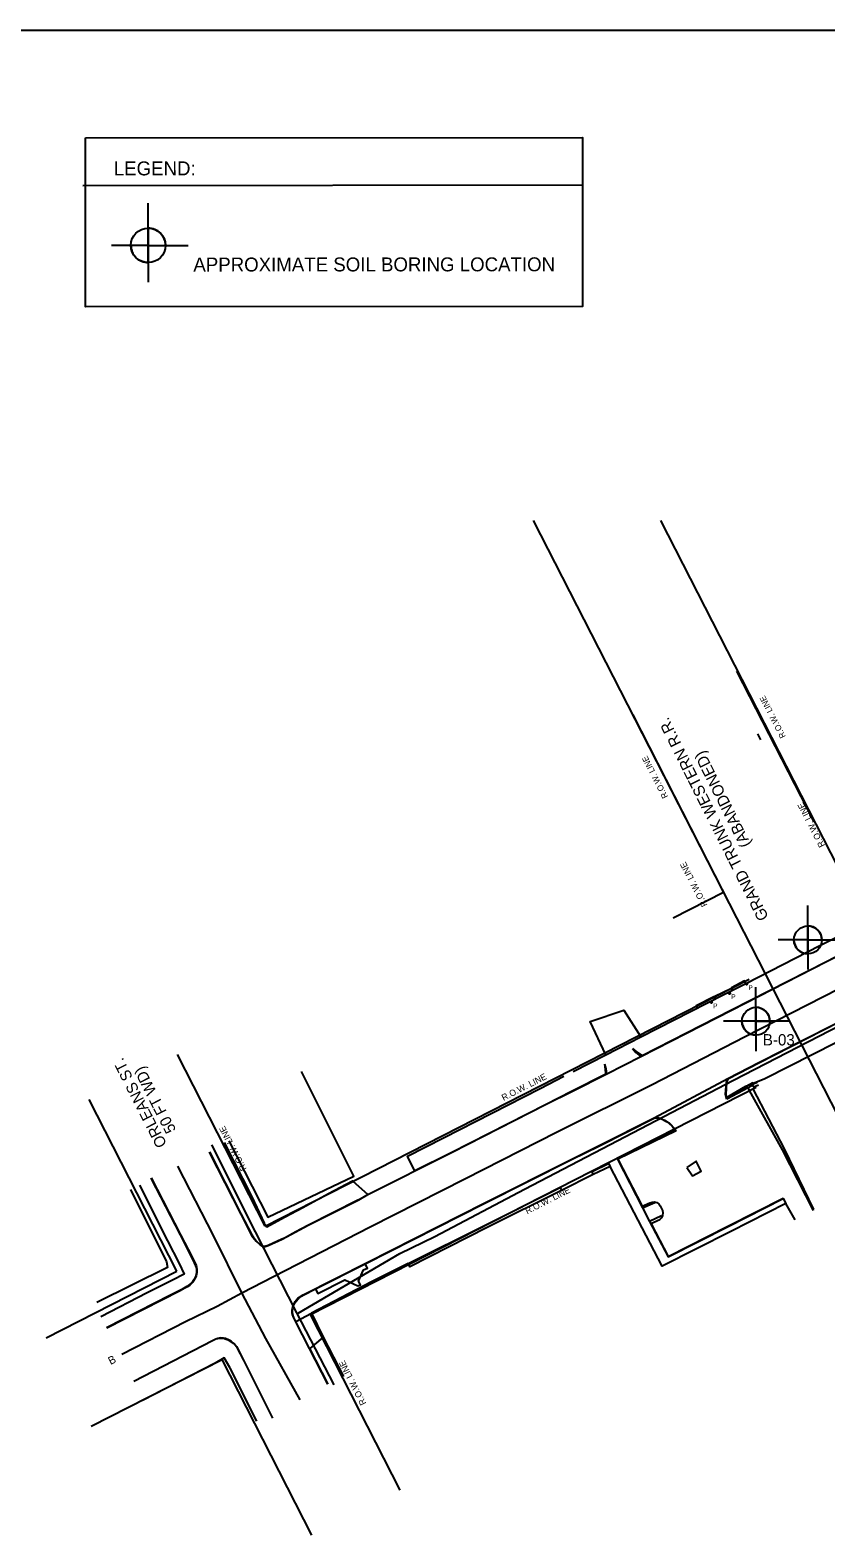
# Model space of a CAD drawing. Extents: x 19007.2 to 19038.3, y 21497.7 to 21516.9.
# Drawn here: x 19024.12 to 19030.11, y 21505.5 to 21516.85 of the extents above; entities that cross this region are included whole.
import ezdxf

# ---------------------------------------------------------------- set-up
doc = ezdxf.new("R2010")
doc.units = 0
for name, color, linetype in [('BORDER', 7, 'Continuous'), ('DETAIL_TEXT_DIMEN_PR', 7, 'Continuous'), ('G-ANNO-TTLB', 7, 'Continuous'), ('TYPICAL_TEXT_DIMEN_PR', 7, 'Continuous'), ('V-ANNO-TEXT', 7, 'Continuous'), ('V-BLDG-OTLN', 7, 'Continuous'), ('V-DEMO-PVMT', 7, 'Continuous'), ('V-PROP-RWAY', 7, 'Continuous'), ('V-PROP-RWAY-IDEN', 7, 'Continuous'), ('V-PVMT-CNTR', 7, 'Continuous'), ('V-PVMT-ROAD', 7, 'Continuous'), ('V-SITE-FEAT-DEMO', 7, 'Continuous'), ('V-SITE-FENC', 7, 'Continuous'), ('V-SITE-STRS', 7, 'Continuous'), ('V-SITE-WALK', 7, 'Continuous'), ('V-UTIL-OVHD', 7, 'Continuous')]:
    doc.layers.add(name, color=color, linetype=linetype)

msp = doc.modelspace()

# ---------------------------------------------------------------- linework, layer by layer
at = {"layer": 'G-ANNO-TTLB'}
msp.add_lwpolyline([(19036.518, 21497.739), (19007.175, 21497.739), (19007.175, 21516.854), (19036.518, 21516.854)], close=True, dxfattribs=at)
at = {"layer": 'TYPICAL_TEXT_DIMEN_PR'}
for p, q in [((19024.513, 21515.685), (19028.274, 21515.688)), ((19025.005, 21515.233), (19025.005, 21515.552)), ((19025.005, 21515.233), (19024.73, 21515.233)), ((19025.005, 21515.233), (19025.006, 21514.957)), ((19025.005, 21515.233), (19025.307, 21515.233)), ((19029.97, 21510.003), (19029.969, 21510.261)), ((19029.97, 21510.003), (19029.746, 21510.003)), ((19029.97, 21510.003), (19030.214, 21510.004)), ((19029.97, 21510.003), (19029.97, 21509.78)), ((19029.579, 21509.39), (19029.578, 21509.648)), ((19029.579, 21509.39), (19029.336, 21509.39)), ((19029.579, 21509.39), (19029.579, 21509.166)), ((19029.823, 21509.39), (19029.579, 21509.39))]:
    msp.add_line(p, q, dxfattribs=at)
msp.add_lwpolyline([(19024.532, 21516.044), (19028.273, 21516.046), (19028.274, 21514.773), (19024.533, 21514.77)], close=True, dxfattribs=at)
for points in [[(19025.005, 21515.363), (19025.005, 21515.233), (19025.135, 21515.233)], [(19025.006, 21515.103), (19025.005, 21515.233), (19024.875, 21515.233)], [(19029.97, 21510.109), (19029.97, 21510.003), (19030.075, 21510.003)], [(19029.97, 21509.898), (19029.97, 21510.003), (19029.864, 21510.003)], [(19029.579, 21509.495), (19029.579, 21509.39), (19029.684, 21509.39)], [(19029.579, 21509.284), (19029.579, 21509.39), (19029.473, 21509.39)]]:
    msp.add_lwpolyline(points, dxfattribs=at)
for centre, radius in [((19025.005, 21515.233), 0.13), ((19029.97, 21510.003), 0.105), ((19029.579, 21509.39), 0.105)]:
    msp.add_circle(centre, radius, dxfattribs=at)
for centre, radius, start, end in [((19025.005, 21515.233), 0.13, 0.0399, 90.0399), ((19025.005, 21515.233), 0.13, 180.0399, 270.0399), ((19029.97, 21510.003), 0.105, 0.0399, 90.0399), ((19029.97, 21510.003), 0.105, 180.0399, 270.0399), ((19029.579, 21509.39), 0.105, 0.0399, 90.0399), ((19029.579, 21509.39), 0.105, 180.0399, 270.0399)]:
    msp.add_arc(centre, radius, start, end, dxfattribs=at)
at = {"layer": 'V-BLDG-OTLN'}
for points in [[(19029.504, 21509.674), (19029.494, 21509.694), (19029.396, 21509.643), (19029.404, 21509.627)], [(19029.268, 21509.559), (19029.261, 21509.574), (19029.13, 21509.507), (19029.137, 21509.492)], [(19029.4, 21509.627), (19029.395, 21509.638), (19029.264, 21509.574), (19029.271, 21509.561)], [(19029.589, 21508.929), (19029.561, 21508.916), (19029.555, 21508.926), (19029.505, 21508.899), (19029.51, 21508.887), (19029.554, 21508.91), (19029.563, 21508.896), (19029.598, 21508.912)], [(19029.875, 21507.894), (19029.805, 21508.018), (19029.389, 21507.808), (19028.873, 21507.546), (19028.481, 21508.297), (19028.355, 21508.236), (19028.115, 21508.115), (19027.557, 21507.836), (19026.975, 21507.542), (19026.962, 21507.566), (19026.685, 21507.428), (19026.233, 21507.192), (19026.323, 21507.01), (19026.474, 21506.714)], [(19028.355, 21508.236), (19028.346, 21508.258), (19028.47, 21508.319), (19028.481, 21508.297)], [(19026.962, 21507.566), (19027.545, 21507.856), (19028.106, 21508.138), (19028.115, 21508.115)], [(19025.823, 21506.378), (19025.619, 21506.783), (19025.578, 21506.856), (19025.509, 21506.815), (19024.963, 21506.535)]]:
    msp.add_lwpolyline(points, dxfattribs=at)
at = {"layer": 'V-DEMO-PVMT'}
for points in [[(19028.193, 21508.862), (19028.458, 21508.995), (19028.585, 21509.06), (19028.712, 21509.125), (19029.395, 21509.474), (19030.111, 21509.839), (19030.748, 21510.163), (19030.799, 21510.192), (19031.091, 21510.345)], [(19028.204, 21509.012), (19028.449, 21509.137), (19028.713, 21509.274), (19029.337, 21509.592), (19029.504, 21509.674), (19030.06, 21509.961), (19030.619, 21510.24), (19030.563, 21510.344)], [(19028.651, 21509.186), (19028.68, 21509.16), (19028.723, 21509.133), (19029.394, 21509.477), (19030.11, 21509.841), (19030.685, 21510.139), (19030.722, 21510.155)], [(19028.4, 21508.455), (19028.813, 21508.662), (19029.367, 21508.959), (19029.601, 21509.079), (19030.324, 21509.447), (19030.834, 21509.706), (19030.982, 21509.779), (19031.298, 21509.941)], [(19029.358, 21508.819), (19029.354, 21508.84), (19029.36, 21508.93), (19029.373, 21508.96), (19029.602, 21509.076), (19030.323, 21509.445), (19030.835, 21509.705), (19030.983, 21509.777)], [(19028.649, 21509.185), (19028.674, 21509.155), (19028.712, 21509.125)], [(19028.192, 21508.863), (19028.449, 21508.993), (19028.446, 21509.03), (19028.442, 21509.066)], [(19028.458, 21508.995), (19028.453, 21509.031), (19028.442, 21509.066)], [(19029.361, 21508.803), (19029.351, 21508.841), (19029.358, 21508.93), (19029.367, 21508.959)], [(19028.401, 21508.453), (19028.813, 21508.66), (19028.82, 21508.662), (19028.833, 21508.664), (19028.847, 21508.662), (19028.873, 21508.652), (19028.908, 21508.633), (19028.924, 21508.622), (19028.948, 21508.6), (19028.958, 21508.588), (19028.964, 21508.58)], [(19028.813, 21508.662), (19028.841, 21508.661), (19028.854, 21508.659), (19028.874, 21508.654), (19028.892, 21508.646), (19028.903, 21508.639), (19028.925, 21508.624), (19028.938, 21508.613), (19028.961, 21508.588), (19028.978, 21508.566)], [(19028.964, 21508.58), (19028.974, 21508.567)]]:
    msp.add_lwpolyline(points, dxfattribs=at)
at = {"layer": 'V-PROP-RWAY'}
for p, q in [((19031.565, 21506), (19027.906, 21513.161)), ((19028.86, 21513.161), (19032.52, 21506.001)), ((19029.433, 21512.026), (19030.015, 21510.891)), ((19028.652, 21511.697), (19029.335, 21510.36)), ((19029.591, 21511.554), (19029.614, 21511.51)), ((19029.335, 21510.36), (19028.957, 21510.167)), ((19025.886, 21507.848), (19029.528, 21509.706)), ((19025.886, 21507.848), (19025.226, 21509.141)), ((19028.966, 21508.581), (19029.581, 21508.895)), ((19025.221, 21507.509), (19024.561, 21508.802)), ((19026.226, 21507.183), (19028.966, 21508.581)), ((19024.236, 21507.006), (19025.221, 21507.509)), ((19026.901, 21505.859), (19026.226, 21507.183)), ((19024.575, 21506.341), (19025.561, 21506.844)), ((19026.237, 21505.519), (19025.561, 21506.844))]:
    msp.add_line(p, q, dxfattribs=at)
at = {"layer": 'V-PVMT-CNTR'}
for points in [[(19024.807, 21506.884), (19025.287, 21507.13), (19025.525, 21507.245), (19025.71, 21507.346), (19025.949, 21507.467), (19026.676, 21507.841), (19027.393, 21508.206), (19028.079, 21508.556), (19028.797, 21508.914), (19029.492, 21509.274), (19030.206, 21509.636), (19030.844, 21509.962), (19031.499, 21510.295), (19032.196, 21510.654), (19032.869, 21510.998), (19033.612, 21511.377), (19034.352, 21511.75), (19035.039, 21512.101), (19035.468, 21512.318)], [(19026.149, 21506.539), (19025.89, 21507.001), (19025.711, 21507.346), (19025.496, 21507.778), (19025.227, 21508.3)]]:
    msp.add_lwpolyline(points, dxfattribs=at)
at = {"layer": 'V-PVMT-ROAD'}
for points in [[(19028.449, 21509.137), (19028.331, 21509.389), (19028.586, 21509.474), (19028.713, 21509.274)], [(19025.465, 21508.404), (19025.701, 21507.938), (19025.782, 21507.78), (19025.792, 21507.764), (19025.818, 21507.735), (19025.846, 21507.709), (19025.865, 21507.697), (19025.875, 21507.694), (19025.885, 21507.694), (19025.908, 21507.702), (19026.014, 21507.749), (19026.21, 21507.854), (19026.591, 21508.045), (19026.657, 21508.085), (19027.289, 21508.402), (19028.001, 21508.766), (19028.193, 21508.862)], [(19027.011, 21508.265), (19027.286, 21508.403), (19027.999, 21508.766), (19028.192, 21508.863)], [(19029.358, 21508.817), (19029.371, 21508.821), (19029.505, 21508.899)], [(19030.012, 21507.964), (19029.778, 21508.422), (19029.543, 21508.847), (19029.52, 21508.889), (19029.361, 21508.803)], [(19028.974, 21508.567), (19028.536, 21508.352), (19028.726, 21507.984), (19028.779, 21507.882), (19028.918, 21507.617), (19029.369, 21507.844), (19029.784, 21508.055), (19029.805, 21508.018)], [(19028.978, 21508.566), (19028.539, 21508.352), (19028.722, 21507.997), (19028.781, 21508.022), (19028.797, 21508.029), (19028.815, 21508.03), (19028.833, 21508.025), (19028.847, 21508.015), (19028.858, 21508), (19028.858, 21508), (19028.876, 21507.966), (19028.879, 21507.947), (19028.877, 21507.928), (19028.868, 21507.911), (19028.855, 21507.898), (19028.848, 21507.893), (19028.791, 21507.864), (19028.919, 21507.619), (19029.368, 21507.846), (19029.785, 21508.057)], [(19025.466, 21508.407), (19025.702, 21507.94), (19025.784, 21507.782), (19025.797, 21507.762), (19025.804, 21507.753), (19025.819, 21507.735), (19025.837, 21507.717), (19025.848, 21507.709), (19025.865, 21507.699), (19025.873, 21507.696), (19025.884, 21507.696), (19025.891, 21507.698), (19025.907, 21507.704), (19026.012, 21507.751), (19026.031, 21507.759), (19026.117, 21507.806), (19026.206, 21507.854), (19026.589, 21508.047)], [(19026.357, 21506.656), (19026.219, 21506.926), (19026.114, 21507.131), (19026.1, 21507.158), (19026.091, 21507.182), (19026.088, 21507.194), (19026.088, 21507.214), (19026.09, 21507.228), (19026.099, 21507.255), (19026.111, 21507.279), (19026.119, 21507.29), (19026.132, 21507.304), (19026.144, 21507.313), (19026.172, 21507.329), (19026.657, 21507.576), (19027.534, 21508.02), (19028.189, 21508.349), (19028.4, 21508.455)], [(19026.116, 21507.13), (19026.101, 21507.159), (19026.096, 21507.171), (19026.091, 21507.195), (19026.091, 21507.215), (19026.093, 21507.228), (19026.102, 21507.255), (19026.111, 21507.272), (19026.118, 21507.283), (19026.135, 21507.302), (19026.158, 21507.321), (19026.171, 21507.328), (19026.263, 21507.375), (19026.638, 21507.564), (19027.534, 21508.018), (19028.19, 21508.348), (19028.401, 21508.453)], [(19029.06, 21508.29), (19029.102, 21508.227), (19029.167, 21508.262), (19029.128, 21508.337), (19029.06, 21508.29)], [(19025.025, 21508.208), (19025.246, 21507.781), (19025.308, 21507.658), (19025.332, 21507.612), (19025.352, 21507.571), (19025.362, 21507.548), (19025.365, 21507.537), (19025.368, 21507.521), (19025.368, 21507.496), (19025.363, 21507.472), (19025.359, 21507.461), (19025.349, 21507.442), (19025.339, 21507.428), (19025.326, 21507.415), (19025.297, 21507.393), (19025.259, 21507.37), (19025.239, 21507.36), (19025.173, 21507.328), (19024.692, 21507.081)], [(19025.028, 21508.21), (19025.248, 21507.782), (19025.335, 21507.614), (19025.355, 21507.573), (19025.365, 21507.55), (19025.368, 21507.539), (19025.371, 21507.522), (19025.371, 21507.497), (19025.365, 21507.472), (19025.359, 21507.455), (19025.347, 21507.435), (19025.34, 21507.426), (19025.328, 21507.412), (19025.319, 21507.404), (19025.3, 21507.39), (19025.281, 21507.379), (19025.24, 21507.358), (19024.693, 21507.078)], [(19024.871, 21508.122), (19025.144, 21507.578), (19025.15, 21507.537), (19024.618, 21507.273)], [(19026.267, 21507.367), (19026.281, 21507.34), (19026.486, 21507.442), (19026.583, 21507.398), (19026.602, 21507.406), (19026.588, 21507.433), (19026.626, 21507.517), (19026.655, 21507.532), (19026.638, 21507.564)], [(19026.116, 21507.13), (19026.233, 21507.192)], [(19025.944, 21506.402), (19025.725, 21506.839), (19025.679, 21506.927), (19025.671, 21506.939), (19025.653, 21506.961), (19025.629, 21506.98), (19025.615, 21506.988), (19025.586, 21507), (19025.571, 21507.004), (19025.548, 21507.005), (19025.528, 21507.001), (19025.515, 21506.997), (19025.488, 21506.984), (19024.897, 21506.678)], [(19025.724, 21506.838), (19025.677, 21506.928), (19025.67, 21506.939), (19025.652, 21506.96), (19025.64, 21506.969), (19025.614, 21506.985), (19025.585, 21506.996), (19025.571, 21507), (19025.548, 21507.001), (19025.528, 21506.999), (19025.515, 21506.995), (19025.488, 21506.983), (19024.898, 21506.677)], [(19026.323, 21507.01), (19026.221, 21506.926)], [(19026.359, 21506.657), (19026.221, 21506.926)]]:
    msp.add_lwpolyline(points, dxfattribs=at)
at = {"layer": 'V-SITE-FEAT-DEMO'}
for centre, radius in [((19029.509, 21509.67), 0.00597), ((19029.509, 21509.67), 0.00299), ((19029.244, 21509.532), 0.00597), ((19029.244, 21509.532), 0.00299), ((19029.38, 21509.601), 0.00597), ((19029.38, 21509.601), 0.00299)]:
    msp.add_circle(centre, radius, dxfattribs=at)
at = {"layer": 'V-SITE-FENC'}
for points in [[(19025.611, 21508.489), (19025.906, 21507.915), (19026.552, 21508.223), (19026.16, 21509.012)], [(19030.014, 21507.973), (19029.794, 21508.429), (19029.559, 21508.88)]]:
    msp.add_lwpolyline(points, dxfattribs=at)
at = {"layer": 'V-SITE-STRS'}
for points in [[(19028.726, 21507.984), (19028.819, 21508.025)], [(19028.868, 21507.925), (19028.779, 21507.882)]]:
    msp.add_lwpolyline(points, dxfattribs=at)
at = {"layer": 'V-SITE-WALK'}
for points in [[(19029.358, 21508.817), (19029.503, 21508.901), (19029.646, 21508.959), (19030.363, 21509.323), (19030.698, 21509.496), (19030.71, 21509.478)], [(19027.01, 21508.266), (19026.956, 21508.374), (19027.228, 21508.513), (19027.955, 21508.884), (19028.134, 21508.976)], [(19025.576, 21508.477), (19025.785, 21508.069), (19025.878, 21507.869), (19025.898, 21507.843), (19026.035, 21507.917), (19026.168, 21507.987), (19026.363, 21508.093), (19026.543, 21508.188), (19026.657, 21508.085)], [(19024.939, 21508.156), (19025.151, 21507.736), (19025.239, 21507.565), (19025.276, 21507.486), (19025.188, 21507.441), (19024.998, 21507.345), (19024.648, 21507.164)]]:
    msp.add_lwpolyline(points, dxfattribs=at)
at = {"layer": 'V-UTIL-OVHD'}
for points in [[(19026.134, 21507.192), (19026.9, 21507.642), (19027.163, 21507.77), (19027.837, 21508.125), (19029.41, 21508.947), (19031.347, 21509.945), (19031.982, 21510.257), (19033.079, 21510.818)], [(19025.481, 21508.46), (19025.809, 21507.805), (19026.12, 21507.195), (19026.402, 21506.653)]]:
    msp.add_lwpolyline(points, dxfattribs=at)

# ---------------------------------------------------------------- texts
msp.add_text('B', height=0.0597, rotation=27.0313).set_placement((19024.722, 21506.801))
at = {"layer": 'BORDER'}
for s, height, p in [('LEGEND:', 0.105, (19024.746, 21515.76)), ('APPROXIMATE SOIL BORING LOCATION', 0.10498, (19025.345, 21515.036))]:
    msp.add_text(s, height=height, rotation=0.0399, dxfattribs=at).set_placement(p)
at = {"layer": 'DETAIL_TEXT_DIMEN_PR'}
msp.add_text('B-03', height=0.085, rotation=0.0399, dxfattribs=at).set_placement((19029.631, 21509.208))
at = {"layer": 'V-ANNO-TEXT'}
for s, height, rotation, p in [('GRAND TRUNK WESTERN R.R.', 0.08503, 116.6596, (19029.677, 21510.173)), ('(ABANDONED)', 0.08503, 116.6596, (19029.544, 21510.724)), ('ORLEANS ST. ', 0.08361, 117.0313, (19025.148, 21508.464)), ('50 FT WD)', 0.0836, 117.0313, (19025.217, 21508.572))]:
    msp.add_text(s, height=height, rotation=rotation, dxfattribs=at).set_placement(p)
at = {"layer": 'V-PROP-RWAY-IDEN'}
for height, rotation, p in [(0.04535, 117.1686, (19029.805, 21511.535)), (0.04535, 117.1686, (19028.919, 21511.082)), (0.04778, 117.0313, (19030.1, 21510.714)), (0.04778, 117.0313, (19029.216, 21510.266)), (0.04778, 27.0313, (19027.68, 21508.79)), (0.04778, 117.0313, (19025.747, 21508.278)), (0.04778, 27.0313, (19027.858, 21507.936)), (0.04778, 117.0313, (19026.648, 21506.513))]:
    msp.add_text('R.O.W. LINE', height=height, rotation=rotation, dxfattribs=at).set_placement(p)
at = {"layer": 'V-SITE-FEAT-DEMO'}
for p in [(19029.522, 21509.625), (19029.393, 21509.557), (19029.257, 21509.488)]:
    msp.add_text('P', height=0.0358, rotation=360, dxfattribs=at).set_placement(p)

doc.saveas('drawing.dxf')
